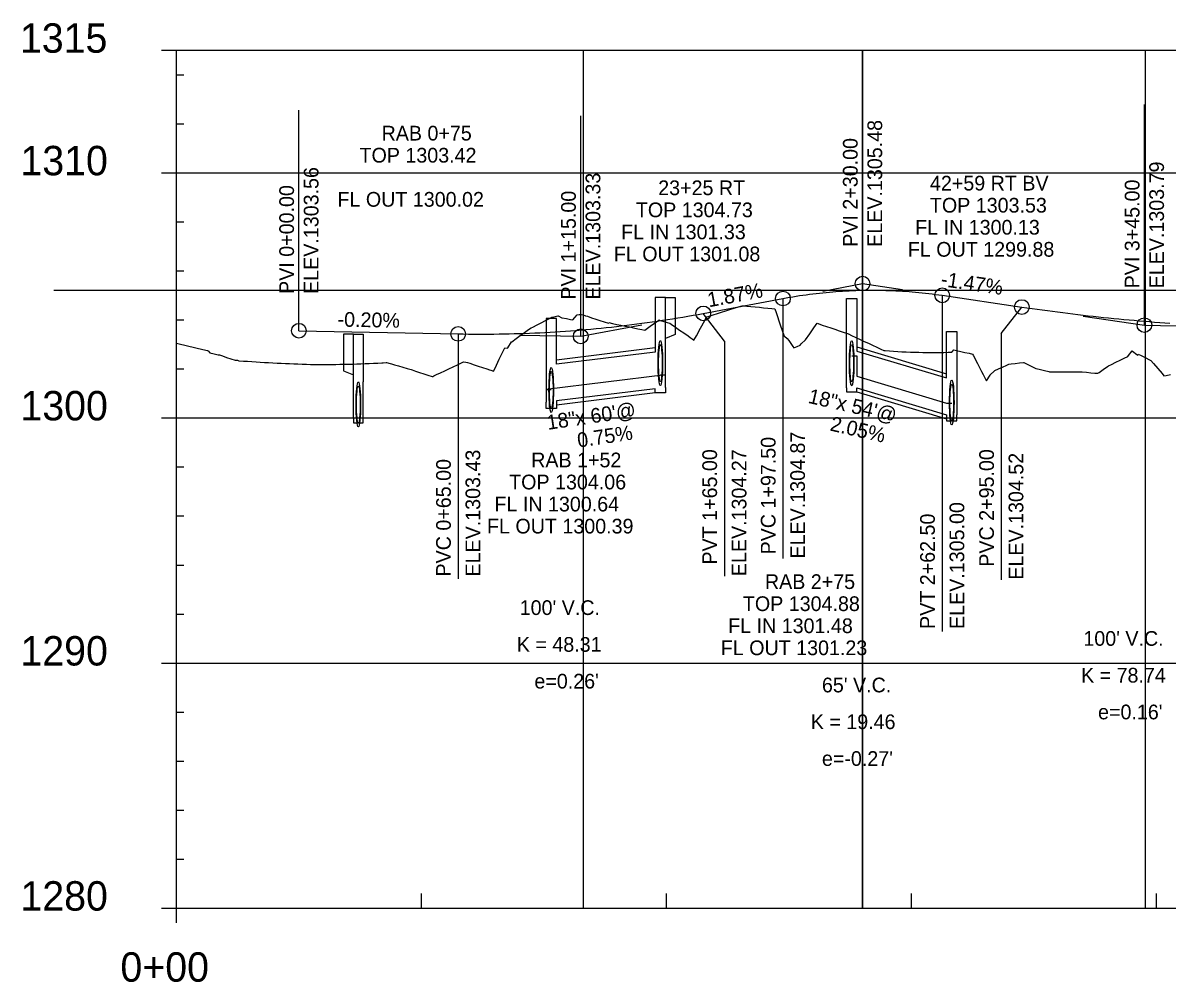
# Model space of a CAD drawing. Extents: x 670877 to 686811, y 705985 to 708501.
# Drawn here: x 685169.6 to 685636.5, y 706297.9 to 706689.3 of the extents above; entities that cross this region are included whole.
import ezdxf

# ---------------------------------------------------------------- set-up
doc = ezdxf.new("R2010")
doc.units = 0
for name, color, linetype in [('30', 7, 'Continuous'), ('37', 7, 'Continuous'), ('63', 7, 'Continuous'), ('DRAINAGE_HGL', 7, 'Continuous'), ('Profile Drainage Annot Left', 7, 'Continuous'), ('Profile Drainage Annotation', 7, 'Continuous'), ('R_Drainage', 7, 'Continuous'), ('R_Drainage Extensions_RIGHT', 7, 'Continuous'), ('R_Exist Surface', 7, 'Continuous'), ('R_No Plot', 7, 'Continuous'), ('R_Vert Alg', 7, 'Continuous'), ('R_Vert Alg Annot', 7, 'Continuous')]:
    doc.layers.add(name, color=color, linetype=linetype)

msp = doc.modelspace()

# ---------------------------------------------------------------- linework, layer by layer
at = {"layer": '37'}
for p, q in [((685226.22, 706678.12), (685232.22, 706678.12)), ((685232.22, 706328.12), (685232.22, 706678.12)), ((685232.22, 706678.12), (685732.22, 706678.12)), ((685232.22, 706668.12), (685235.22, 706668.12)), ((685232.22, 706648.12), (685235.22, 706648.12)), ((685226.22, 706628.12), (685232.22, 706628.12)), ((685232.22, 706628.12), (685732.22, 706628.12)), ((685232.22, 706608.12), (685235.22, 706608.12)), ((685232.22, 706588.12), (685235.22, 706588.12)), ((685232.22, 706568.12), (685235.22, 706568.12)), ((685232.22, 706548.12), (685235.22, 706548.12)), ((685226.22, 706528.12), (685232.22, 706528.12)), ((685232.22, 706528.12), (685732.22, 706528.12)), ((685232.22, 706508.12), (685235.22, 706508.12)), ((685232.22, 706488.12), (685235.22, 706488.12)), ((685232.22, 706468.12), (685235.22, 706468.12)), ((685232.22, 706448.12), (685235.22, 706448.12)), ((685226.22, 706428.12), (685232.22, 706428.12)), ((685232.22, 706428.12), (685732.22, 706428.12)), ((685232.22, 706408.12), (685235.22, 706408.12)), ((685232.22, 706388.12), (685235.22, 706388.12)), ((685232.22, 706368.12), (685235.22, 706368.12)), ((685232.22, 706348.12), (685235.22, 706348.12)), ((685332.22, 706328.12), (685332.22, 706334.12)), ((685432.22, 706328.12), (685432.22, 706334.12)), ((685532.22, 706328.12), (685532.22, 706334.12)), ((685632.22, 706328.12), (685632.22, 706334.12)), ((685226.22, 706328.12), (685232.22, 706328.12)), ((685232.22, 706328.12), (685732.22, 706328.12)), ((685232.22, 706322.12), (685232.22, 706328.12))]:
    msp.add_line(p, q, dxfattribs=at)
at = {"layer": 'DRAINAGE_HGL'}
for points in [[(685507.79, 706553.52), (685509.91, 706553.52), (685509.91, 706545.16), (685509.91, 706545.16), (685546.54, 706534.16), (685548.62, 706534.16)], [(685429.72, 706545.72), (685431.79, 706545.72), (685431.79, 706545.72), (685431.79, 706545.72), (685383.07, 706539.72), (685385.18, 706539.72)]]:
    msp.add_lwpolyline(points, dxfattribs=at)
at = {"layer": 'Profile Drainage Annot Left'}
msp.add_line((685232.22, 706328.12), (685282.22, 706328.12), dxfattribs=at)
at = {"layer": 'R_Drainage'}
for points in [[(685431.79, 706577.22), (685427.65, 706577.22)], [(685427.65, 706577.22), (685427.65, 706555.01)], [(685431.79, 706540.52), (685431.79, 706577.22)], [(685505.68, 706540.42), (685505.68, 706576.92)], [(685505.68, 706576.92), (685509.91, 706576.92)], [(685509.91, 706576.92), (685509.91, 706555.42)], [(685387.28, 706568.72), (685383.07, 706568.72)], [(685383.07, 706568.72), (685383.07, 706534.52)], [(685387.28, 706550.04), (685387.28, 706568.72)], [(685546.54, 706544.42), (685546.54, 706563.42)], [(685546.54, 706563.42), (685550.71, 706563.42)], [(685550.71, 706563.42), (685550.71, 706529.42)], [(685304.48, 706562.32), (685300.48, 706562.32), (685300.48, 706547.32), (685304.48, 706545.65), (685304.48, 706562.32)], [(685304.48, 706528.32), (685304.48, 706562.32)], [(685304.48, 706562.32), (685308.48, 706562.32)], [(685308.48, 706562.32), (685308.48, 706542.82)], [(685427.65, 706556.68), (685387.28, 706551.71)], [(685427.65, 706555.01), (685387.28, 706550.04)], [(685509.91, 706557.09), (685546.54, 706546.09)], [(685509.91, 706555.42), (685546.54, 706544.42)], [(685308.48, 706526.15), (685308.48, 706542.82)], [(685427.65, 706540.01), (685387.28, 706535.04)], [(685427.65, 706538.34), (685427.65, 706540.01)], [(685431.79, 706540.52), (685431.79, 706538.34)], [(685505.68, 706540.42), (685505.68, 706538.75)], [(685509.91, 706538.75), (685509.91, 706540.42)], [(685509.91, 706540.42), (685546.54, 706529.42)], [(685427.65, 706538.34), (685387.28, 706533.37)], [(685387.28, 706535.04), (685387.28, 706532.02)], [(685431.79, 706538.34), (685427.65, 706538.34)], [(685505.68, 706538.75), (685509.91, 706538.75)], [(685509.91, 706538.75), (685546.54, 706527.75)], [(685383.07, 706532.02), (685383.07, 706534.52)], [(685387.28, 706532.02), (685383.07, 706532.02)], [(685304.48, 706528.32), (685304.48, 706526.15)], [(685304.48, 706526.15), (685308.48, 706526.15)], [(685546.54, 706529.42), (685546.54, 706526.92)], [(685546.54, 706526.92), (685550.71, 706526.92)], [(685550.71, 706526.92), (685550.71, 706529.42)]]:
    msp.add_lwpolyline(points, dxfattribs=at)
for centre, major_axis in [((685429.72, 706550.52), (0, 9.17)), ((685507.79, 706550.42), (0, 9.17)), ((685429.72, 706550.52), (0, 7.5)), ((685507.79, 706550.42), (0, 7.5)), ((685385.18, 706539.52), (0, 9.17)), ((685385.18, 706539.52), (0, 7.5)), ((685306.48, 706533.65), (0, 9.17)), ((685306.48, 706533.65), (0, 7.5)), ((685548.62, 706534.42), (0, 9.17)), ((685548.62, 706534.42), (0, 7.5))]:
    msp.add_ellipse(centre, major_axis=major_axis, ratio=0.1, dxfattribs=at)
at = {"layer": 'R_Drainage Extensions_RIGHT'}
msp.add_lwpolyline([(685431.79, 706577.22), (685435.79, 706577.22), (685435.79, 706562.22), (685431.79, 706560.55), (685431.79, 706577.22)], dxfattribs=at)
at = {"layer": 'R_Exist Surface'}
msp.add_lwpolyline([(685232.22, 706558.63), (685233.93, 706558.2), (685235.64, 706557.78), (685237.35, 706557.36), (685239.06, 706556.94), (685240.77, 706556.54), (685242.49, 706556.13), (685244.2, 706555.74), (685244.89, 706555.58), (685245.03, 706555.56), (685245.14, 706555.51), (685245.85, 706554.74), (685245.91, 706554.72), (685247.62, 706554.27), (685249.33, 706553.92), (685249.78, 706553.86), (685251.04, 706553.41), (685252.75, 706552.81), (685254.47, 706552.22), (685256.16, 706551.65), (685256.18, 706551.65), (685257.24, 706551.72), (685257.67, 706551.49), (685257.89, 706551.47), (685259.6, 706551.35), (685261.31, 706551.23), (685263.02, 706551.11), (685264.73, 706551), (685266.45, 706550.9), (685268.16, 706550.79), (685269.87, 706550.7), (685271.58, 706550.6), (685273.29, 706550.52), (685275, 706550.44), (685276.71, 706550.36), (685278.43, 706550.29), (685280.14, 706550.22), (685280.44, 706550.21), (685281.85, 706550.15), (685283.56, 706550.09), (685285.27, 706550.03), (685286.98, 706549.98), (685287.38, 706549.97), (685288.7, 706549.96), (685290.41, 706549.96), (685292.12, 706549.96), (685293.83, 706549.96), (685295.54, 706549.98), (685297.25, 706549.99), (685298.96, 706550.01), (685300.68, 706550.04), (685302.39, 706550.08), (685304.1, 706550.12), (685305.81, 706550.16), (685307.52, 706550.21), (685309.23, 706550.27), (685310.93, 706550.33), (685310.94, 706550.33), (685312.66, 706550.42), (685314.37, 706550.52), (685316.08, 706550.62), (685316.67, 706550.66), (685317.79, 706550.73), (685317.93, 706550.74), (685319.5, 706550.34), (685319.99, 706550.22), (685321.21, 706549.85), (685322.92, 706549.34), (685324.64, 706548.83), (685326.35, 706548.32), (685328.06, 706547.82), (685328.49, 706547.69), (685329.77, 706547.26), (685331.48, 706546.69), (685333.19, 706546.13), (685334.9, 706545.59), (685336.62, 706545.05), (685336.81, 706544.99), (685337.23, 706545.31), (685338.33, 706545.81), (685340.04, 706546.59), (685341.75, 706547.38), (685343.46, 706548.18), (685345.17, 706548.99), (685346.88, 706549.81), (685348.34, 706550.51), (685348.6, 706550.64), (685349.37, 706551.05), (685350.31, 706550.88), (685351, 706550.76), (685352.02, 706550.41), (685353.73, 706549.84), (685355.44, 706549.28), (685357.15, 706548.72), (685358.87, 706548.17), (685360, 706547.8), (685360.58, 706547.58), (685361.65, 706547.17), (685362.29, 706548.49), (685364, 706552.07), (685365.71, 706555.66), (685366.22, 706556.73), (685367.35, 706556.58), (685367.42, 706556.69), (685369.04, 706559.12), (685369.13, 706559.19), (685370.85, 706560.47), (685372.56, 706561.72), (685374.27, 706562.95), (685375.98, 706564.15), (685376.98, 706564.83), (685377.69, 706565.2), (685379.4, 706566.09), (685381.11, 706566.98), (685382.83, 706567.86), (685384.54, 706568.75), (685385.41, 706569.2), (685386.25, 706569.41), (685387.83, 706569.82), (685387.96, 706569.76), (685389.45, 706569.02), (685389.67, 706568.98), (685391.38, 706568.65), (685393.09, 706568.31), (685393.94, 706568.14), (685394.81, 706569.12), (685395.72, 706570.2), (685396.52, 706570.3), (685396.77, 706570.33), (685397.11, 706570.37), (685397.34, 706570.38), (685397.52, 706570.37), (685398.23, 706570.14), (685399.22, 706569.83), (685399.94, 706569.59), (685401.65, 706569.03), (685403.36, 706568.47), (685405.07, 706567.92), (685406.79, 706567.38), (685408.5, 706566.84), (685408.58, 706566.81), (685408.73, 706567.01), (685410.21, 706566.68), (685411.92, 706566.31), (685413.63, 706565.94), (685415.34, 706565.58), (685417.06, 706565.23), (685418.77, 706564.88), (685420.48, 706564.53), (685422.19, 706564.2), (685423.43, 706563.96), (685423.9, 706564.29), (685425.61, 706565.51), (685427.32, 706566.75), (685429.04, 706568.01), (685429.19, 706568.12), (685429.55, 706567.89), (685430.75, 706567.57), (685432.46, 706567.12), (685433.57, 706566.82), (685434.17, 706566.4), (685435.88, 706565.19), (685437.59, 706563.99), (685439.3, 706562.78), (685441.02, 706561.58), (685441.91, 706560.94), (685442.73, 706560.33), (685443.44, 706559.79), (685444.44, 706561.62), (685446.15, 706564.77), (685447.86, 706567.94), (685448.61, 706569.34), (685448.63, 706569.36), (685449.27, 706569.57), (685449.57, 706569.66), (685451.28, 706570.21), (685453, 706570.75), (685454.71, 706571.28), (685456.42, 706571.82), (685458.13, 706572.35), (685459.84, 706572.88), (685461.55, 706573.4), (685463.16, 706573.89), (685463.24, 706573.91), (685463.26, 706573.91), (685463.61, 706573.88), (685464.98, 706573.76), (685466.69, 706573.6), (685468.4, 706573.43), (685470.11, 706573.26), (685471.82, 706573.09), (685473.53, 706572.92), (685475.24, 706572.74), (685476.45, 706572.62), (685476.96, 706571.13), (685478.67, 706566.12), (685480.23, 706561.55), (685480.38, 706561.43), (685481.48, 706560.53), (685482.09, 706559.66), (685483.8, 706557.22), (685484.18, 706556.69), (685485.51, 706557.29), (685486.79, 706557.86), (685487.23, 706558.31), (685488.94, 706560.04), (685488.94, 706560.04), (685490.65, 706562.47), (685492.36, 706564.88), (685493.7, 706566.75), (685494.07, 706566.62), (685495.78, 706566.03), (685497.49, 706565.44), (685499.21, 706564.86), (685500.92, 706564.28), (685502.63, 706563.7), (685504.34, 706563.12), (685506.05, 706562.55), (685506.41, 706562.43), (685506.48, 706562.41), (685507.76, 706561.79), (685509.47, 706560.98), (685511.19, 706560.17), (685512.9, 706559.37), (685514.61, 706558.58), (685516.32, 706557.79), (685518.03, 706557.02), (685519.74, 706556.25), (685520.97, 706555.7), (685521.45, 706555.66), (685523.17, 706555.51), (685524.88, 706555.38), (685526.59, 706555.25), (685526.59, 706555.25), (685528.3, 706555.16), (685530.01, 706555.09), (685531.72, 706555.02), (685533.43, 706554.96), (685535.15, 706554.92), (685536.86, 706554.88), (685538.57, 706554.86), (685540.28, 706554.85), (685541.99, 706554.84), (685543.7, 706554.85), (685545.41, 706554.87), (685547.13, 706554.9), (685548.71, 706554.94), (685548.84, 706555.12), (685549.4, 706555.91), (685550.55, 706555.63), (685552.26, 706555.24), (685553.97, 706554.85), (685555.68, 706554.49), (685557.14, 706554.19), (685557.4, 706553.7), (685559.11, 706550.38), (685560.82, 706547.06), (685561.42, 706545.9), (685562.53, 706543.7), (685562.76, 706543.25), (685564.24, 706545.54), (685564.36, 706545.73), (685565.95, 706547.25), (685566.15, 706547.45), (685567.66, 706548.13), (685569.38, 706548.9), (685571.09, 706549.69), (685571.85, 706550.05), (685572.8, 706550.15), (685574.51, 706550.35), (685576.22, 706550.56), (685577.93, 706550.78), (685577.99, 706550.79), (685579.64, 706549.94), (685581.36, 706549.08), (685582.99, 706548.27), (685583.07, 706548.25), (685584.78, 706547.83), (685586.49, 706547.42), (685588.2, 706547.03), (685588.55, 706546.95), (685589.91, 706546.92), (685591.62, 706546.89), (685593.34, 706546.87), (685595.05, 706546.87), (685596.76, 706546.88), (685598.47, 706546.9), (685600.18, 706546.94), (685601.74, 706546.99), (685601.89, 706546.97), (685603.6, 706546.77), (685605.32, 706546.59), (685607.03, 706546.43), (685608.18, 706546.33), (685608.74, 706546.72), (685610.45, 706547.9), (685612.16, 706549.08), (685612.54, 706549.34), (685613.87, 706549.99), (685615.58, 706550.82), (685617.3, 706551.66), (685619.01, 706552.51), (685620.42, 706553.22), (685620.72, 706553.6), (685622.21, 706555.49), (685622.43, 706555.33), (685624.14, 706554.04), (685624.53, 706553.76), (685624.72, 706554.2), (685625.85, 706553.6), (685627.57, 706552.72), (685629.28, 706551.86), (685629.91, 706551.55), (685630.99, 706550.27), (685632.7, 706548.25), (685634.41, 706546.23), (685635.2, 706545.29), (685636.12, 706545.48), (685637.83, 706545.84)], dxfattribs=at)
at = {"layer": 'R_No Plot'}
for p, q in [((685398.29, 706328.12), (685398.29, 706678.12)), ((685512.22, 706328.12), (685512.22, 706678.12)), ((685512.27, 706328.12), (685512.27, 706678.12)), ((685627.73, 706328.12), (685627.73, 706678.12)), ((685182.22, 706580.22), (685782.22, 706580.22))]:
    msp.add_line(p, q, dxfattribs=at)
at = {"layer": 'R_Vert Alg'}
for p, q in [((685495.97, 706579.9), (685512.22, 706582.94)), ((685512.22, 706582.94), (685528.47, 706580.55)), ((685447.22, 706570.78), (685479.72, 706576.86)), ((685544.72, 706578.15), (685577.22, 706573.36)), ((685602.22, 706569.68), (685627.22, 706565.99)), ((685282.22, 706563.72), (685347.22, 706562.42)), ((685397.22, 706561.42), (685422.22, 706566.1)), ((685627.22, 706565.99), (685652.22, 706565.49)), ((685372.22, 706561.92), (685397.22, 706561.42))]:
    msp.add_line(p, q, dxfattribs=at)
for points in [[(685479.72, 706576.86), (685481.07, 706577.11), (685482.43, 706577.35), (685483.78, 706577.58), (685485.13, 706577.8), (685486.49, 706578.01), (685487.84, 706578.21), (685489.2, 706578.4), (685490.55, 706578.58), (685491.9, 706578.76), (685493.26, 706578.92), (685494.61, 706579.08), (685495.97, 706579.22), (685497.32, 706579.36), (685498.68, 706579.48), (685500.03, 706579.6), (685501.38, 706579.71), (685502.74, 706579.8), (685504.09, 706579.89), (685505.45, 706579.97), (685506.8, 706580.04), (685508.15, 706580.1), (685509.51, 706580.15), (685510.86, 706580.19), (685513.57, 706580.25), (685514.93, 706580.26), (685516.28, 706580.26), (685517.63, 706580.26), (685518.99, 706580.24), (685520.34, 706580.22), (685521.7, 706580.18), (685523.05, 706580.14), (685524.4, 706580.08), (685525.76, 706580.02), (685527.11, 706579.95), (685528.47, 706579.87), (685529.82, 706579.78), (685531.18, 706579.68), (685532.53, 706579.57), (685533.88, 706579.45), (685535.24, 706579.32), (685536.59, 706579.18), (685537.95, 706579.03), (685539.3, 706578.87), (685540.65, 706578.71), (685542.01, 706578.53), (685543.36, 706578.35), (685544.72, 706578.15)], [(685577.22, 706573.36), (685579.3, 706573.06), (685581.38, 706572.76), (685583.47, 706572.47), (685585.55, 706572.18), (685587.63, 706571.9), (685589.72, 706571.62), (685591.8, 706571.35), (685593.88, 706571.08), (685595.97, 706570.82), (685598.05, 706570.57), (685600.13, 706570.32), (685602.22, 706570.08), (685604.3, 706569.84), (685606.38, 706569.61), (685608.47, 706569.38), (685610.55, 706569.16), (685612.63, 706568.94), (685614.72, 706568.73), (685616.8, 706568.53), (685618.88, 706568.33), (685620.97, 706568.13), (685623.05, 706567.95), (685625.13, 706567.76), (685629.3, 706567.41), (685631.38, 706567.25), (685633.47, 706567.09), (685635.55, 706566.93), (685637.63, 706566.78)], [(685347.22, 706562.42), (685349.3, 706562.38), (685351.38, 706562.35), (685353.47, 706562.34), (685355.55, 706562.33), (685357.63, 706562.32), (685359.72, 706562.33), (685361.8, 706562.35), (685363.88, 706562.37), (685365.97, 706562.41), (685368.05, 706562.45), (685370.13, 706562.51), (685372.22, 706562.57), (685374.3, 706562.64), (685376.38, 706562.72), (685378.47, 706562.81), (685380.55, 706562.9), (685382.63, 706563.01), (685384.72, 706563.13), (685386.8, 706563.25), (685388.88, 706563.38), (685390.97, 706563.53), (685393.05, 706563.68), (685395.13, 706563.84), (685399.3, 706564.19), (685401.38, 706564.38), (685403.47, 706564.57), (685405.55, 706564.78), (685407.63, 706564.99), (685409.72, 706565.22), (685411.8, 706565.45), (685413.88, 706565.69), (685415.97, 706565.94), (685418.05, 706566.2), (685420.13, 706566.47), (685422.22, 706566.75), (685424.3, 706567.03), (685426.38, 706567.33), (685428.47, 706567.63), (685430.55, 706567.95), (685432.63, 706568.27), (685434.72, 706568.6), (685436.8, 706568.94), (685438.88, 706569.29), (685440.97, 706569.65), (685443.05, 706570.02), (685445.13, 706570.39), (685447.22, 706570.78)]]:
    msp.add_lwpolyline(points, dxfattribs=at)
for centre in [(685512.22, 706582.94), (685479.72, 706576.86), (685544.72, 706578.15), (685447.22, 706570.78), (685577.22, 706573.36), (685627.22, 706565.99), (685282.22, 706563.72), (685347.22, 706562.42), (685397.22, 706561.42)]:
    msp.add_circle(centre, 3, dxfattribs=at)
at = {"layer": 'R_Vert Alg Annot'}
for p, q in [((685512.22, 706582.94), (685512.22, 706672.94)), ((685282.22, 706563.72), (685282.22, 706653.72)), ((685627.22, 706565.99), (685627.22, 706655.99)), ((685397.22, 706561.42), (685397.22, 706651.42)), ((685479.72, 706576.86), (685479.72, 706470.77)), ((685544.72, 706578.12), (685544.72, 706441.03)), ((685568.83, 706562.63), (685577.22, 706573.36)), ((685455.84, 706559.44), (685447.22, 706570.78)), ((685347.22, 706562.42), (685347.22, 706462.42)), ((685455.84, 706559.44), (685455.84, 706463.57)), ((685568.83, 706562.63), (685568.83, 706462.13))]:
    msp.add_line(p, q, dxfattribs=at)

# ---------------------------------------------------------------- texts
at = {"layer": '30'}
for s, p in [('1315', (685168.38, 706677.12)), ('1310', (685168.59, 706627.12)), ('1300', (685168.59, 706527.12)), ('1290', (685168.59, 706427.12)), ('1280', (685168.59, 706327.12)), ('0+00', (685209.4, 706298.12))]:
    msp.add_text(s, height=12, dxfattribs=at).set_placement(p)
at = {"layer": '63'}
for p in [(685182.22, 706328.12), (685232.22, 706328.12)]:
    msp.add_text('-', height=0.0001, dxfattribs=at).set_placement(p)
at = {"layer": 'Profile Drainage Annotation'}
for s, p in [('RAB 0+75', (685315.96, 706641.31)), ('TOP 1303.42', (685306.96, 706632.31)), ('23+25 RT', (685428.84, 706619.02)), ('42+59 RT BV', (685539.73, 706620.91)), ('FL OUT 1300.02', (685297.96, 706614.31)), ('TOP 1304.73', (685419.72, 706610.02)), ('TOP 1303.53', (685539.7, 706611.91)), ('FL IN 1301.33', (685413.72, 706601.02)), ('FL IN 1300.13', (685533.7, 706602.91)), ('FL OUT 1301.08', (685410.74, 706592.02)), ('FL OUT 1299.88', (685530.71, 706593.91)), ('RAB 1+52', (685377.01, 706507.98)), ('TOP 1304.06', (685368.02, 706498.98)), ('FL IN 1300.64', (685362.02, 706489.98)), ('FL OUT 1300.39', (685358.99, 706480.98)), ('RAB 2+75', (685472.38, 706458.34)), ('TOP 1304.88', (685463.39, 706449.34)), ('FL IN 1301.48', (685457.39, 706440.34)), ('FL OUT 1301.23', (685454.38, 706431.34))]:
    msp.add_text(s, height=6, dxfattribs=at).set_placement(p)
for s, rotation, p in [('18"x 54\'@ ', 347.0821, (685489.68, 706534.32)), ('18"x 60\'@ ', 8.4536, (685383.83, 706523.24)), (' 2.05%', 347.0821, (685496.44, 706523.54)), (' 0.75%', 8.4536, (685394.05, 706515.66))]:
    msp.add_text(s, height=6, rotation=rotation, dxfattribs=at).set_placement(p)
at = {"layer": 'R_Vert Alg Annot'}
for s, rotation, p in [('ELEV.1305.48', 90, (685520.22, 706597.94)), ('PVI 2+30.00', 90, (685510.22, 706597.94)), ('ELEV.1303.56', 90, (685290.22, 706578.72)), ('ELEV.1303.79', 90, (685635.22, 706580.99)), ('ELEV.1303.33', 90, (685405.22, 706576.42)), ('PVI 3+45.00', 90, (685625.22, 706580.99)), ('PVI 0+00.00', 90, (685280.22, 706578.72)), ('PVI 1+15.00', 90, (685395.22, 706576.42)), ('-1.47%', 351.6164, (685543.9, 706581.97)), ('1.87%', 10.5999, (685449.53, 706573.25)), ('-0.20%', 358.8542, (685297.96, 706565.41)), ('ELEV.1304.87', 90, (685488.72, 706470.77)), ('PVC 1+97.50', 90, (685476.72, 706472.44)), ('ELEV.1303.43', 90, (685356.22, 706463.42)), ('PVT 1+65.00', 90, (685452.84, 706468.3)), ('ELEV.1304.27', 90, (685464.84, 706463.57)), ('PVC 2+95.00', 90, (685565.83, 706467.42)), ('ELEV.1304.52', 90, (685577.83, 706462.13)), ('PVC 0+65.00', 90, (685344.22, 706463.42)), ('ELEV.1305.00', 90, (685553.72, 706442.03)), ('PVT 2+62.50', 90, (685541.72, 706442.03))]:
    msp.add_text(s, height=6, rotation=rotation, dxfattribs=at).set_placement(p)
for s, p in [("100' V.C.", (685372.32, 706447.73)), ('K = 48.31', (685371.16, 706432.73)), ("100' V.C.", (685602.32, 706435.16)), ("e=0.26'", (685378.32, 706417.73)), ('K = 78.74', (685601.38, 706420.16)), ("65' V.C.", (685495.65, 706416.17)), ("e=0.16'", (685608.32, 706405.16)), ('K = 19.46', (685491.1, 706401.17)), ("e=-0.27'", (685495.65, 706386.17))]:
    msp.add_text(s, height=6, dxfattribs=at).set_placement(p)

doc.saveas('drawing.dxf')
